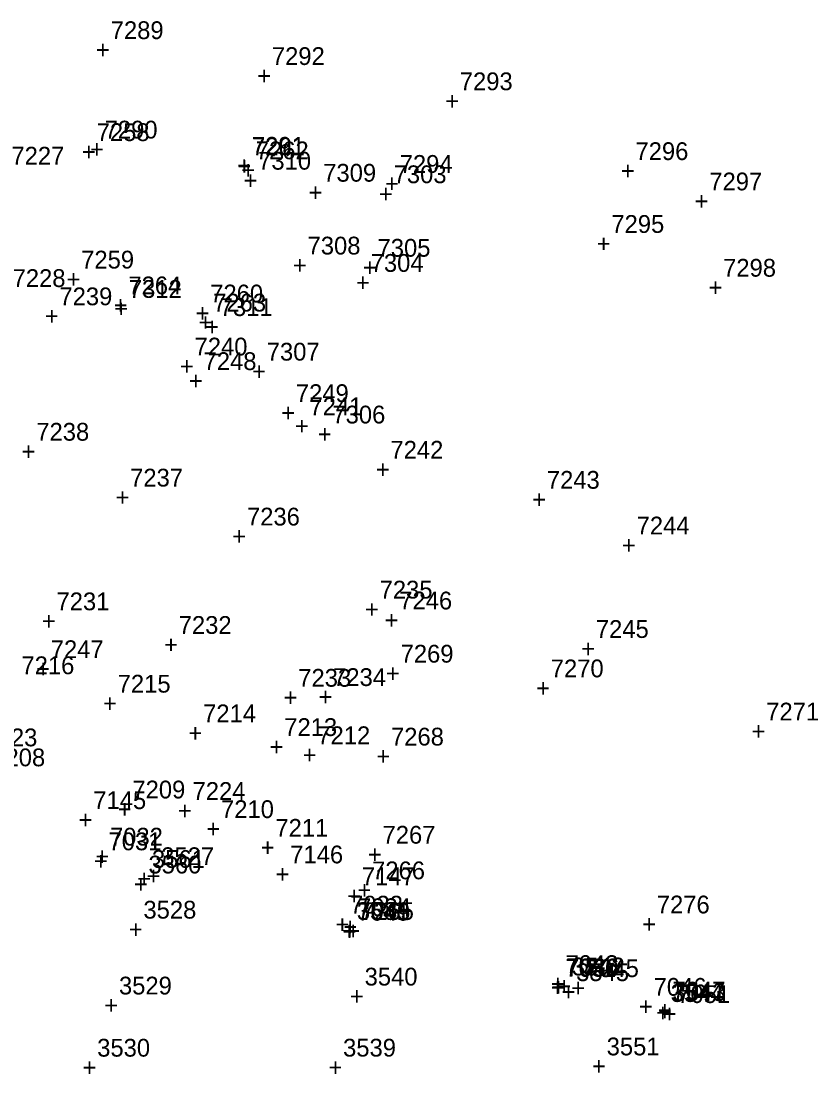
# Model space of a CAD drawing. Extents: x 1136220 to 1137808, y 528804 to 531215.
# Drawn here: x 1137225.4 to 1137337.5, y 530031.8 to 530179.8 of the extents above; entities that cross this region are included whole.
import ezdxf

# ---------------------------------------------------------------- set-up
doc = ezdxf.new("R2010")
doc.units = 0
for name, color, linetype in [('S_Buildings_SillElevation', 7, 'Continuous'), ('S_Curb_Type_1', 7, 'Continuous'), ('S_Drainage_CB', 7, 'Continuous'), ('S_Drainage_Sump', 7, 'Continuous'), ('S_Fencing_Picket', 7, 'Continuous'), ('S_Ground_Elevation', 7, 'Continuous'), ('S_RetWall_Top', 7, 'Continuous'), ('S_Roadway_Centerline', 7, 'Continuous'), ('S_Roadway_Drive_Gravel', 7, 'Continuous'), ('S_Roadway_Drive_Paved', 7, 'Continuous'), ('S_Roadway_Edge_Pavement', 7, 'Continuous'), ('S_Roadway_Sidewalks', 7, 'Continuous'), ('S_Trees_Bush', 7, 'Continuous'), ('S_Trees_Decid_NonPay', 7, 'Continuous'), ('S_Trees_Decid_Pay', 7, 'Continuous'), ('S_Utilities_GuyWire3', 7, 'Continuous'), ('S_Utilities_Pole_Joint', 7, 'Continuous')]:
    doc.layers.add(name, color=color, linetype=linetype)

msp = doc.modelspace()

# ---------------------------------------------------------------- texts
at = {"layer": 'S_Buildings_SillElevation'}
for s, p in [('7305', (1137275.55, 530146.71)), ('+', (1137273.49, 530143.96))]:
    msp.add_text(s, height=2.5, dxfattribs=at).set_placement(p)
at = {"layer": 'S_Curb_Type_1'}
for s, p in [('7032', (1137237.93, 530063.9)), ('+', (1137235.87, 530061.15)), ('7033', (1137271.68, 530054.34)), ('7034', (1137272.8, 530053.98)), ('+', (1137269.62, 530051.59)), ('+', (1137270.74, 530051.23)), ('7043', (1137301.98, 530045.98)), ('7045', (1137304.85, 530045.4)), ('+', (1137299.92, 530043.23)), ('+', (1137302.79, 530042.65)), ('7046', (1137314.36, 530042.78)), ('7047', (1137317.03, 530042.25)), ('+', (1137312.3, 530040.03)), ('+', (1137314.97, 530039.51))]:
    msp.add_text(s, height=2.5, dxfattribs=at).set_placement(p)
at = {"layer": 'S_Drainage_CB'}
for s, p in [('3560', (1137243.34, 530059.98)), ('+', (1137241.28, 530057.23))]:
    msp.add_text(s, height=2.5, dxfattribs=at).set_placement(p)
at = {"layer": 'S_Drainage_Sump'}
for s, p in [('3561', (1137243.83, 530060.76)), ('+', (1137241.77, 530058.01))]:
    msp.add_text(s, height=2.5, dxfattribs=at).set_placement(p)
at = {"layer": 'S_Fencing_Picket'}
for s, p in [('7215', (1137239.01, 530085.41)), ('+', (1137236.95, 530082.66)), ('7213', (1137262.43, 530079.31)), ('+', (1137260.37, 530076.56))]:
    msp.add_text(s, height=2.5, dxfattribs=at).set_placement(p)
at = {"layer": 'S_Ground_Elevation'}
for s, p in [('7227', (1137224.07, 530159.66)), ('7310', (1137258.76, 530158.95)), ('7309', (1137267.91, 530157.26)), ('+', (1137256.7, 530156.2)), ('7303', (1137277.81, 530157.05)), ('+', (1137265.85, 530154.51)), ('+', (1137275.74, 530154.3)), ('7308', (1137265.71, 530147.02)), ('+', (1137263.65, 530144.27)), ('7304', (1137274.58, 530144.58)), ('7228', (1137224.24, 530142.45)), ('7312', (1137240.58, 530140.92)), ('+', (1137272.52, 530141.83)), ('7239', (1137230.82, 530139.88)), ('7311', (1137253.36, 530138.37)), ('+', (1137228.76, 530137.13)), ('+', (1137238.52, 530138.17)), ('+', (1137251.3, 530135.62)), ('7240', (1137249.82, 530132.82)), ('7307', (1137259.97, 530132.1)), ('+', (1137247.76, 530130.07)), ('+', (1137257.91, 530129.35)), ('7241', (1137265.98, 530124.42)), ('7306', (1137269.2, 530123.26)), ('7238', (1137227.57, 530120.84)), ('+', (1137263.92, 530121.67)), ('+', (1137267.14, 530120.51)), ('+', (1137225.51, 530118.09)), ('7242', (1137277.36, 530118.31)), ('7237', (1137240.76, 530114.39)), ('+', (1137275.3, 530115.56)), ('7243', (1137299.35, 530114.08)), ('+', (1137238.7, 530111.64)), ('+', (1137297.29, 530111.33)), ('7236', (1137257.19, 530108.91)), ('7244', (1137311.97, 530107.65)), ('+', (1137255.13, 530106.16)), ('+', (1137309.91, 530104.9)), ('7235', (1137275.84, 530098.64)), ('7231', (1137230.41, 530096.99)), ('7246', (1137278.6, 530097.11)), ('+', (1137273.78, 530095.89)), ('+', (1137228.35, 530094.24)), ('7232', (1137247.59, 530093.67)), ('+', (1137276.53, 530094.36)), ('7245', (1137306.24, 530093.1)), ('+', (1137245.53, 530090.92)), ('+', (1137304.17, 530090.35)), ('7216', (1137225.48, 530088)), ('7233', (1137264.4, 530086.24)), ('7234', (1137269.3, 530086.34)), ('+', (1137262.34, 530083.49)), ('+', (1137267.24, 530083.59)), ('7214', (1137251.02, 530081.24)), ('+', (1137248.95, 530078.49)), ('7212', (1137267.08, 530078.16)), ('7208', (1137221.38, 530075.05)), ('+', (1137265.02, 530075.41)), ('7209', (1137241.08, 530070.53)), ('+', (1137239.02, 530067.78)), ('7210', (1137253.54, 530067.77)), ('+', (1137251.48, 530065.02)), ('7211', (1137261.18, 530065.14)), ('+', (1137259.12, 530062.39)), ('3528', (1137242.63, 530053.63)), ('+', (1137240.57, 530050.88)), ('3540', (1137273.73, 530044.22)), ('+', (1137271.67, 530041.47)), ('3530', (1137236.13, 530034.22)), ('3551', (1137307.76, 530034.4)), ('+', (1137305.7, 530031.65)), ('+', (1137234.07, 530031.47))]:
    msp.add_text(s, height=2.5, dxfattribs=at).set_placement(p)
at = {"layer": 'S_RetWall_Top'}
for s, p in [('7262', (1137258.43, 530160.41)), ('+', (1137256.37, 530157.66)), ('7264', (1137240.51, 530141.42)), ('+', (1137238.45, 530138.67)), ('7263', (1137252.44, 530139)), ('+', (1137250.38, 530136.25))]:
    msp.add_text(s, height=2.5, dxfattribs=at).set_placement(p)
at = {"layer": 'S_Roadway_Centerline'}
for s, p in [('3529', (1137239.19, 530042.96)), ('+', (1137237.13, 530040.21)), ('3539', (1137270.7, 530034.23)), ('+', (1137268.64, 530031.48))]:
    msp.add_text(s, height=2.5, dxfattribs=at).set_placement(p)
at = {"layer": 'S_Roadway_Drive_Gravel'}
for s, p in [('7258', (1137236.05, 530162.97)), ('7261', (1137257.9, 530160.97)), ('+', (1137233.99, 530160.22)), ('+', (1137255.84, 530158.22)), ('7259', (1137233.88, 530145.05)), ('+', (1137231.82, 530142.3)), ('7260', (1137252.02, 530140.28)), ('+', (1137249.96, 530137.53)), ('7269', (1137278.79, 530089.63)), ('7270', (1137299.9, 530087.56)), ('+', (1137276.73, 530086.88)), ('+', (1137297.84, 530084.81)), ('7271', (1137330.19, 530081.49)), ('7268', (1137277.44, 530077.97)), ('+', (1137328.13, 530078.74)), ('+', (1137275.38, 530075.22))]:
    msp.add_text(s, height=2.5, dxfattribs=at).set_placement(p)
at = {"layer": 'S_Roadway_Drive_Paved'}
for s, p in [('7267', (1137276.25, 530064.17)), ('+', (1137274.19, 530061.42)), ('7266', (1137274.78, 530059.16)), ('+', (1137272.72, 530056.41)), ('7265', (1137273.22, 530053.44)), ('7276', (1137314.81, 530054.36)), ('+', (1137312.75, 530051.61)), ('+', (1137271.15, 530050.69))]:
    msp.add_text(s, height=2.5, dxfattribs=at).set_placement(p)
at = {"layer": 'S_Roadway_Edge_Pavement'}
for s, p in [('7289', (1137238.03, 530177.31)), ('+', (1137235.96, 530174.56)), ('7292', (1137260.69, 530173.67)), ('+', (1137258.63, 530170.92)), ('7293', (1137287.11, 530170.12)), ('+', (1137285.05, 530167.37)), ('7290', (1137237.18, 530163.33)), ('+', (1137235.12, 530160.58)), ('7291', (1137257.88, 530161.05)), ('7296', (1137311.81, 530160.3)), ('+', (1137255.82, 530158.3)), ('7294', (1137278.66, 530158.5)), ('+', (1137309.75, 530157.55)), ('7297', (1137322.19, 530156.04)), ('+', (1137276.6, 530155.75)), ('+', (1137320.13, 530153.29)), ('7295', (1137308.42, 530150.06)), ('+', (1137306.36, 530147.31)), ('7298', (1137324.13, 530143.9)), ('+', (1137322.07, 530141.15)), ('7031', (1137237.72, 530063.24)), ('3527', (1137245.13, 530061.15)), ('+', (1137235.66, 530060.49)), ('+', (1137243.07, 530058.4)), ('3541', (1137272.63, 530053.45)), ('7035', (1137272.72, 530053.44)), ('7049', (1137272.7, 530053.34)), ('+', (1137270.57, 530050.7)), ('+', (1137270.64, 530050.59)), ('+', (1137270.66, 530050.69)), ('7050', (1137301.96, 530045.45)), ('7036', (1137302.06, 530045.52)), ('3542', (1137302.86, 530045.64)), ('+', (1137299.89, 530042.7)), ('+', (1137300, 530042.77)), ('+', (1137300.8, 530042.89)), ('3543', (1137317.04, 530042.04)), ('7051', (1137317.68, 530041.76)), ('+', (1137314.98, 530039.29)), ('+', (1137315.62, 530039.01))]:
    msp.add_text(s, height=2.5, dxfattribs=at).set_placement(p)
at = {"layer": 'S_Roadway_Sidewalks'}
for s, p in [('7145', (1137235.58, 530069.03)), ('+', (1137233.52, 530066.28)), ('7146', (1137263.27, 530061.4)), ('+', (1137261.21, 530058.65)), ('7147', (1137273.34, 530058.33)), ('+', (1137271.28, 530055.58))]:
    msp.add_text(s, height=2.5, dxfattribs=at).set_placement(p)
at = {"layer": 'S_Trees_Bush'}
for s, p in [('7249', (1137264.06, 530126.27)), ('+', (1137262, 530123.52)), ('7247', (1137229.6, 530090.26)), ('+', (1137227.54, 530087.51))]:
    msp.add_text(s, height=2.5, dxfattribs=at).set_placement(p)
at = {"layer": 'S_Trees_Decid_NonPay'}
for s, p in [('7248', (1137251.09, 530130.77)), ('+', (1137249.03, 530128.02))]:
    msp.add_text(s, height=2.5, dxfattribs=at).set_placement(p)
at = {"layer": 'S_Trees_Decid_Pay'}
for s, p in [('7223', (1137220.28, 530077.86)), ('7224', (1137249.54, 530070.32)), ('+', (1137247.48, 530067.57))]:
    msp.add_text(s, height=2.5, dxfattribs=at).set_placement(p)
at = {"layer": 'S_Utilities_GuyWire3'}
for s, p in [('3544', (1137316.76, 530041.91)), ('+', (1137314.7, 530039.16))]:
    msp.add_text(s, height=2.5, dxfattribs=at).set_placement(p)
at = {"layer": 'S_Utilities_Pole_Joint'}
for s, p in [('3545', (1137303.47, 530044.84)), ('+', (1137301.41, 530042.09))]:
    msp.add_text(s, height=2.5, dxfattribs=at).set_placement(p)

doc.saveas('drawing.dxf')
